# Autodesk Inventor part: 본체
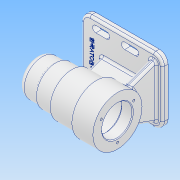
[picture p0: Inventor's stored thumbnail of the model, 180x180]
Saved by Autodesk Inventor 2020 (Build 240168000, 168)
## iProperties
Created: 2021-10
Part Number: 본체
Material: 알루미늄 6061
Document SubType Name: Modeling
Designer: user
Density: 2.7 g/cm^3
Appearance: 알루미늄 - 평지
Mass: 690.248 g
Surface Area: 701.718 cm^2
Volume: 255.647 cm^3
Author: user
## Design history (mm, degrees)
sketch "스케치1"
  geometry: L1 (-56, 0)-(56, 0); L2 (-56, 0)-(-56, 7.5); L3 (-53, 10.5)-(-53, 10.5); L4 (-53, 10.5)-(-53, 15.7); L5 (-52.7, 16)-(-49, 16); L6 (-49, 16)-(-49, 17.2); L7 (-48.7, 17.5)-(-31, 17.5); L8 (-31, 17.5)-(-31, 21); L9 (-31, 21)-(-19, 21); L10 (-19, 21)-(-19, 21); L11 (-16, 24)-(32, 24); L12 (35, 21)-(35, 21); L13 (35, 21)-(50, 21); L14 (-56, 0)-(-62, 0); L15 (-62, 0)-(-62, 25); L16 (-62, 25)-(-38, 25); L17 (-38, 25)-(-38, 27); L18 (-38, 27)-(-16, 27); L19 (-16, 27)-(-16, 27); L20 (-13, 30)-(18, 30); L21 (18, 30)-(18, 31); L22 (21, 34)-(50, 34); L23 (50, 34)-(50, 21); A1 r 0.3 centre (-52.7, 15.7) between (-52.7, 16) and (-53, 15.7); A2 r 0.3 centre (-48.7, 17.2) between (-48.7, 17.5) and (-49, 17.2); A3 r 3 centre (-53, 7.5) between (-53, 10.5) and (-56, 7.5); A4 r 3 centre (-16, 21) between (-16, 24) and (-19, 21); A5 r 3 centre (32, 21) between (35, 21) and (32, 24); A6 r 3 centre (21, 31) between (21, 34) and (18, 31); A7 r 3 centre (-13, 27) between (-13, 30) and (-16, 27); 11 further points
  constraints: 46 end point, 17 perpendicular, 14 point on circle, 14 tangent, 10 point on line, 7 centre point, 4 vertical, 3 equal radius, 2 coincident, 2 horizontal, 1 midpoint
  dimensions: "d3" = 112 distance of L1.start L1.end; "d4" = 10.5 distance of L1.start point (-56, 10.5); "d5" = 3 distance of point (-56, 10.5) L3.end; "d6" = 4 distance of point (-53, 16) L5.end; "d7" = 18 distance of point (-49, 17.5) L7.end; "d8" = 12 distance of L8.end L9.end; "d9" = 32 diameter of L5 L1; "d10" = 35 diameter of L7 L1; "d11" = 42 diameter of L9 L1; "d12" = 54 distance of point (-19, 24) point (35, 24); "d13" = 48 diameter of L11 L1; "d14" = 15 distance of L12.end L13.end; "d15" = 42 diameter of L13 L1; "d16" = 0.3 radius of A1; "d17" = 3 radius of A3; "d18" = 3 radius of A4 (derived); "d19" = 112 distance between parallel lines of L23 L15; "d20" = 24 distance of L15.end L16.end; "d21" = 46 distance between parallel lines of L19 L15; "d22" = 80 distance between parallel lines of L21 L15; "d24" = 50 diameter of L16 L1; "d25" = 54 diameter of L18 L1; "d26" = 60 diameter of L20 L1; "d27" = 68 diameter of L22 L1; "d28" = 3 radius of A6 (derived)
revolve "회전1" sketch "스케치1" stored, may be unused: angle "d29" = 90 deg
fillet "모깎기1" dims "d30" = 8
fillet "모깎기2" dims "d31" = 3
node "작업 평면1"
sketch "스케치2"
  geometry: L1 (-50, 45)-(38, 45); L2 (50, 33)-(50, -33); L3 (38, -45)-(-50, -45); L4 (-62, -33)-(-62, 33); L5 (-62, 45)-(50, -45); L6 (50, 45)-(-62, -45); L7 (50, -34)-(50, 34) reference; A1 r 12 centre (-50, 33) between (-50, 45) and (-62, 33); A2 r 12 centre (38, 33) between (50, 33) and (38, 45); A3 r 12 centre (38, -33) between (38, -45) and (50, -33); A4 r 12 centre (-50, -33) between (-62, -33) and (-50, -45); 3 further points
  constraints: 12 end point, 8 point on circle, 8 point on line, 8 tangent, 4 centre point, 3 equal radius, 3 midpoint, 2 parallel, 1 collinear, 1 horizontal, 1 horizontal alignment, 1 perpendicular
  dimensions: "d33" = 112 distance of L5.end L6.end; "d34" = 90 distance of L6.start L5.end; "d35" = 12 radius of A1
extrude "돌출1" join sketch "스케치2" distance "d36" = 8; taper "d37" = 0 deg
sketch "스케치3"
  geometry: L1 (50, -33)-(50, 33) reference; L2 (-35, 4)-(42, 4); L3 (42, 4)-(42, -4); L4 (42, -4)-(-35, -4); L5 (-35, -4)-(-35, 4); L6 (-35, 4)-(42, -4); L7 (42, 4)-(-35, -4); 3 further points
  constraints: 12 end point, 3 midpoint, 2 parallel, 1 horizontal, 1 horizontal alignment, 1 perpendicular
  dimensions: "d38" = 77 distance of L3.end L4.end; "d39" = 8 distance of L2.end L3.end; "d40" = 8 distance between parallel lines of L1 L3
extrude "돌출2" join sketch "스케치3" stored distance "d41" = 8; taper "d42" = 0 deg
sketch "스케치4"
  geometry: L1 (0, 0)-(-28.236, 0) reference; L2 (0, 8)-(-28.236, 8) reference; L3 (-37.342, -19.409)-(0, -33); L4 (-37.342, 27.409)-(0, 41); L5 (0, -29)-(0, -41) reference; L6 (0, 49)-(0, 37) reference; L7 (8, -40.314)-(0, -40.314) reference; L8 (0, -40.314)-(0, 0) reference; L9 (0, 0)-(-28.236, 0) reference; L10 (-28.236, 8)-(0, 8) reference; L11 (0, 8)-(0, 48.314) reference; L12 (0, 48.314)-(8, 48.314) reference; L13 (8, 48.314)-(8, -40.314) reference; L14 (0, 0)-(0, 8) reference; C1 r 21 at (-62, 4) reference; A1 r 34 centre (-62, 4) between (-28.236, 8) and (-28.236, 0) reference; A2 r 34 centre (-62, 4) between (-28.236, 0) and (-28.236, 8) reference; A3 r 34 centre (-62, 4) between (-28.236, 8) and (-28.236, 0) reference
  constraints: 4 end point, 2 point on circle, 2 point on line
  dimensions: "d43" = 8 distance of L5.end L3.end; "d44" = 8 distance of L6.start L4.end; "d45" = 110 deg angle of L3 L8; "d46" = 110 deg angle of L11 L4
extrude "돌출3" join sketch "스케치4" distance "d47" = 8; taper "d48" = 0 deg
feature "면 기울기1" dims angle "d49" = 15 deg
sketch "스케치5"
  geometry: L1 (-62, 33)-(-62, -33) reference; L2 (-50, -45)-(38, -45) reference; L3 (-42, -33)-(-27, -33); L4 (-42, -37.5)-(-27, -37.5); L5 (-27, -28.5)-(-42, -28.5); L6 (42, -37)-(34, -37) reference; L7 (34, -37)-(34, -4) reference; L8 (34, -4)-(-35, -4) reference; L9 (-35, -4)-(-35, 4) reference; L10 (-35, 4)-(34, 4) reference; L11 (34, 4)-(34, 37) reference; L12 (34, 37)-(42, 37) reference; L13 (42, 37)-(42, -37) reference; L14 (38, -45)-(-50, -45) reference; L15 (-62, -33)-(-62, 33) reference; L16 (-50, 45)-(38, 45) reference; L17 (50, 33)-(50, -33) reference; L18 (-2, -33)-(13, -33); L19 (-2, -37.5)-(13, -37.5); L20 (13, -28.5)-(-2, -28.5); L21 (-42, 33)-(-27, 33); L22 (-42, 28.5)-(-27, 28.5); L23 (-27, 37.5)-(-42, 37.5); L24 (-2, 33)-(13, 33); L25 (-2, 28.5)-(13, 28.5); L26 (13, 37.5)-(-2, 37.5); A1 r 4.5 centre (-42, -33) between (-42, -28.5) and (-42, -37.5); A2 r 4.5 centre (-27, -33) between (-27, -37.5) and (-27, -28.5); A3 r 12 centre (-50, -33) between (-62, -33) and (-50, -45) reference; A4 r 12 centre (-50, 33) between (-50, 45) and (-62, 33) reference; A5 r 12 centre (38, 33) between (50, 33) and (38, 45) reference; A6 r 12 centre (38, -33) between (38, -45) and (50, -33) reference; A7 r 4.5 centre (-2, -33) between (-2, -28.5) and (-2, -37.5); A8 r 4.5 centre (13, -33) between (13, -37.5) and (13, -28.5); A9 r 4.5 centre (-42, 33) between (-42, 37.5) and (-42, 28.5); A10 r 4.5 centre (-27, 33) between (-27, 28.5) and (-27, 37.5); A11 r 4.5 centre (-2, 33) between (-2, 37.5) and (-2, 28.5); A12 r 4.5 centre (13, 33) between (13, 28.5) and (13, 37.5); 5 further points
  constraints: 32 end point, 16 point on circle, 16 tangent, 8 centre point, 6 parallel, 4 midpoint, 2 point on line, 1 horizontal
  dimensions: "d50" = 15 distance of L3.start L3.end; "d51" = 9 diameter of A2; "d54" = 20 distance from line of L15 L3.start; "d55" = 33 vertical distance of point (0, 0) point (-34.5, -33); "d56" = 15 distance of L18.start L18.end; "d57" = 9 diameter of A8; "d58" = 15 distance of L21.start L21.end; "d59" = 9 diameter of A10; "d60" = 15 distance of L24.start L24.end; "d61" = 9 diameter of A12; "d62" = 60 distance from line of L1 L18.start; "d63" = 33 vertical distance of point (0, 0) point (5.5, -33); "d64" = 20 distance of L1.start L21.start; "d65" = 33 vertical distance of point (0, 0) point (-34.5, 33); "d66" = 60 distance from line of L1 L24.start
extrude "돌출4" cut sketch "스케치5" distance "d67" = 300; taper "d68" = 0 deg
sketch "스케치6"
  geometry: C1 r 34 at (0, 0) reference; 1 further point
  constraints: 1 vertical alignment
  dimensions: "d69" = 26 distance of point (0, -26) C1.centre
hole "구멍1" sketch "스케치6" at (0, -26) diameter "d70" = 3.242; stored, may be unused: countersink angle "d74" = 90 deg, drill point angle "d76" = 118 deg; dims "d71" = 8, "d72" = 4, "d73" = 2, "d75" = 11
fillet "모깎기3" dims "d80" = 3
fillet "모깎기4" dims "d81" = 3
fillet "모깎기5" dims "d82" = 3
chamfer "모따기1" distance "d83" = 1; stored, may be unused: second distance "d84" = 2, angle "d85" = 45 deg
sketch "스케치7"
  geometry: L1 (-59, -33)-(-59, 33) reference; 2 further points
  constraints: 1 horizontal alignment, 1 other
  dimensions: "d86" = 12 distance from line of L1 point (-47, 0)
feature "엠보싱1" sketch "스케치7" dims "d3" = 112, "d4" = 10.5, "d5" = 3, "d6" = 4, "d7" = 18, "d8" = 12, "d9" = 32, "d10" = 35, "d11" = 42, "d12" = 54, "d13" = 48, "d14" = 15, "d15" = 42, "d16" = 0.3, "d17" = 3, "d18" = 3 (derived), "d19" = 112, "d20" = 24, "d21" = 46, "d22" = 80, "d24" = 50, "d25" = 54, "d26" = 60, "d27" = 68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
fillet "모깎기6" dims "d89" = 0.3
node "솔리드1"
pattern_circular "원형 패턴1" dims angle "d78" = 360 deg
node "절단 모서리 투영1"
node "절단 모서리 투영2"
feature "A9D066F2-1C7D-4E18-AEED-F7BC21143FA4" dims "d70" = 3.242, "d71" = 8, "d72" = 4, "d73" = 2, "d74" = 90 deg, "d75" = 11, "d76" = 118 deg
